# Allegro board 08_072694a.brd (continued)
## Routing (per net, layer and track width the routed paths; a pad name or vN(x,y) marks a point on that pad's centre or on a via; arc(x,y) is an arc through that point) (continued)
Net_82: length 0.9
  TOP w0.254: 125.22,56.64 v1(124.59,56.01)
PGOOD1: length 68
  TOP w0.254: R1.1 66.17,60.33 v1(66.68,59.82) U1.A8
  L5-INT3 w0.254: v1(66.68,59.82) 67.32,59.18 67.32,58.08 67.74,57.66 68.86,57.66 69.82,56.69 69.82,49.04 40.61,19.83 TP6.1
PGOOD2: length 37.2
  TOP w0.254: R16.1 37.46,60.33 v1(37.97,59.82) U2.A8
  L5-INT3 w0.254: TP21.1 33.56,61.21 34.96,59.82 v1(37.97,59.82)
PGOOD3: length 90.4
  TOP w0.254: R30.1 95.38,60.33 v1(95.88,59.82) U3.A8
  L4-INT2 w0.254: TP29.1 160.55,48.89 124.21,48.89 120.61,52.49 120.61,55.69 117.12,59.18 U3.A8 v1(95.88,59.82)
PGOOD4: length 54.4
  TOP w0.254: R44.1 124.08,60.33 v1(124.59,59.82) U4.A8
  L4-INT2 w0.254: v1(124.59,59.82) 125.2,59.21 163.35,59.21 TP37.1
RUN: length 163.6
  TOP w0.254: U1.B8 v1(67.94,59.82)
  L4-INT2 w0.254: v1(34.67,63.64) 22.31,63.64 2.11,43.44 2.11,33.07 TP5.1 2.42,27.44 2.42,22.71 P1.2
  L5-INT3 w0.254: v1(34.67,63.64) 34.67,63.18 37.39,60.46 67.19,60.46 67.84,59.82 v1(67.94,59.82) 68.53,59.23 86.08,59.23 87.98,57.34 91.35,57.34 v1(91.82,57.81) 112.76,57.81 116.88,61.93 v1(120.52,61.93)
  BOTTOM w0.254: v1(91.82,57.81) 92.33,58.32 R32.2 ; v1(34.67,63.64) 34.67,61.84 R18.2 ; v1(120.52,61.93) 120.68,61.77 R46.2
SOFTSTART: length 104.2
  TOP w0.254: U1.A11 v1(66.68,63.63) 65.91,62.86 C6.2 ; C32.2 37.21,62.86 v1(37.97,63.63) U2.A11 ; U4.A11 v1(124.59,63.63) 123.82,62.86 C78.2 ; U3.A11 v1(95.88,63.63) 95.12,62.86 C55.2
  L4-INT2 w0.254: v1(37.97,63.63) 38.63,62.97 56.04,62.97 56.55,62.46 56.99,62.46 57.5,62.97 62.03,62.97 62.38,62.61 65.66,62.61 v1(66.68,63.63) U1.A11 95.25,62.99 v1(95.88,63.63) 96.55,62.97 118.87,62.97 119.36,63.46 119.86,63.46 120.35,62.97 123.93,62.97 v1(124.59,63.63)
SYNC1: length 68.6
  TOP w0.254: U1.B6 v1(67.94,56.01) ; R58.2 v1(64.9,56.26)
  L3-INT1 w0.254: v1(64.9,56.26) 65.24,56.6 67.35,56.6 v1(67.94,56.01)
  L5-INT3 w0.254: v1(64.9,56.26) 64.21,55.58 64.21,50.75 24.46,11 TP8.1
UNNAMED_1_ADLTM4712_I1_COMPB: length 4.3
  TOP w0.254: U1.B11 v1(67.94,63.63)
  BOTTOM w0.203: R10.1 66,64.26 66.04,64.26
  BOTTOM w0.254: v1(67.94,63.63) 67.31,64.26 66.04,64.26
UNNAMED_1_ADLTM4712_I1_EXTVCC: length 10.6
  TOP w0.254: U1.B4 v1(67.94,53.47)
  BOTTOM w0.254: 67.27,55.08 67.31,55.04 67.31,54.1 v1(67.94,53.47) ; 67.27,55.08 C95.2 ; 67.27,55.08 66.97,55.38 66.19,55.38 65.91,55.66 63.85,55.66 63.17,56.34 R11.1
UNNAMED_1_ADLTM4712_I1_FREQ: length 3.6
  TOP w0.254: R3.2 64.35,58.55 v1(66.68,58.55) U1.A7
UNNAMED_1_ADLTM4712_I1_ISET: length 5.3
  TOP w0.254: U1.B5 v1(67.94,54.74) ; R6.2 v1(64.95,54.61)
  L3-INT1 w0.254: v1(67.94,54.74) 67.35,55.34 65.68,55.34 v1(64.95,54.61)
UNNAMED_1_ADLTM4712_I1_PHMODE: length 5.5
  TOP w0.254: U1.A9 v1(66.68,61.09)
  BOTTOM w0.254: v1(66.68,61.09) 66.04,60.45 66.04,58.71 R5.2 65.65,58.27 R4.1
UNNAMED_1_ADLTM4712_I1_SW1: length 3.6
  TOP w0.254: U1.K5 v1(79.38,54.74) U1.L5 v1(80.64,54.74)
  BOTTOM w0.254: U1.K5 v1(79.38,54.74)
UNNAMED_1_ADLTM4712_I1_SW2: length 3.6
  TOP w0.254: v1(80.64,59.82) U1.L8 v1(79.38,59.82) U1.K8
  BOTTOM w0.254: U1.K8 v1(79.38,59.82)
UNNAMED_1_ADLTM4712_I1_VOUT: length 130
  TOP w0.254: U1.H12 v1(76.84,64.9) ; U1.M12 v1(81.91,64.9) ; U1.K11 v1(79.38,63.63) ; U1.M11 v1(81.91,63.63) ; U1.L12 v1(80.64,64.9) ; U1.K12 v1(79.38,64.9) ; U1.L11 v1(80.64,63.63) ; U1.J12 v1(78.1,64.9) ; U1.J11 v1(78.1,63.63) ; U1.H11 v1(76.84,63.63)
  L3-INT1 w0.254: TP17.1 94.14,97.16 88.93,91.94 88.93,81.25 85.24,77.57 76.84,77.57 75.84,76.58 75.84,66.93 76.43,66.34 v2(77.44,66.34)
  L6-INT4 w0.254: 66.93,65.66 76.07,65.66 v1(76.84,64.9) ; 66.93,65.66 63.79,65.66 60.3,62.17 v1(60.3,57.55) ; 66.93,65.66 66.94,65.67 v1(66.94,68.72) 66.93,68.73 ; v2(79.5,76.33) 78.05,77.77 69.27,77.77 58.29,66.8 58.29,55.55 59.99,53.85 60.96,53.85 v1(61.34,54.23)
  BOTTOM w0.254: C14.2 v1(66.94,68.72) ; R11.2 v1(60.3,57.55) ; v1(61.34,54.23) 61.72,54.61 R13.1
  vias: v2(77.44,67.46) v2(78.49,75.44) v2(78.49,74.14) v2(78.46,73.02) v2(78.49,71.93) v2(78.49,69.54) v2(78.51,70.66) v2(78.51,68.45) v2(80.04,73.81) v2(80.9,76.33) v2(81.16,73.79) v2(82.17,73.79) v2(82.3,76.33) v2(83.82,76.33)
UNNAMED_1_CAP_I39_N1: length 1.7
  BOTTOM w0.254: R7.2 61.89,61.9 C11.1
UNNAMED_1_CN3P_I129_N3: length 4
  BOTTOM w0.254: R8.1 7.38,16.44 R9.2 5.07,18.08 P1.3
UNNAMED_1_CN3P_I130_N1: length 3
  BOTTOM w0.508: R2.2 8.01,43.05 P2.1
UNNAMED_2_ADLTM4712_I17_COMPA: length 23.4
  TOP w0.254: U2.B10 v1(39.24,62.36)
  L5-INT3 w0.254: v1(56.77,62.99) 39.88,62.99 v1(39.24,62.36)
  BOTTOM w0.254: v1(56.77,62.99) 57.57,63.79 R59.1 ; v1(39.24,62.36) 38.61,62.99 36.87,62.99 R23.2
UNNAMED_2_ADLTM4712_I17_COMPB: length 4.3
  TOP w0.254: U2.B11 v1(39.24,63.63)
  BOTTOM w0.254: v1(39.24,63.63) 38.61,64.26 37.3,64.26 R23.1
UNNAMED_2_ADLTM4712_I17_EXTVCC: length 10
  TOP w0.254: U2.B4 v1(39.24,53.47)
  BOTTOM w0.254: R24.1 34.46,56.35 35.26,55.55 36.88,55.55 37.09,55.35 38.37,55.35 38.57,55.15 ; C97.2 38.57,55.15 ; 38.57,55.15 38.62,55.09 38.62,54.09 v1(39.24,53.47)
UNNAMED_2_ADLTM4712_I17_FB: length 8
  TOP w0.254: U2.B9 v1(39.24,61.09)
  BOTTOM w0.254: v1(39.24,61.09) 39.88,61.72 39.88,66.33 R25.2 39.88,67.89 R26.2
UNNAMED_2_ADLTM4712_I17_FREQ: length 3.6
  TOP w0.254: R19.2 35.65,58.55 v1(37.97,58.55) U2.A7
UNNAMED_2_ADLTM4712_I17_ISET: length 5.3
  TOP w0.254: R22.2 v1(36.22,54.61) ; U2.B5 v1(39.24,54.74)
  L3-INT1 w0.254: v1(39.24,54.74) 38.62,55.36 36.97,55.36 v1(36.22,54.61)
UNNAMED_2_ADLTM4712_I17_PHMODE: length 5.5
  TOP w0.254: U2.A9 v1(37.97,61.09)
  BOTTOM w0.254: v1(37.97,61.09) 36.92,60.03 R21.2 36.95,58.27 R20.1
UNNAMED_2_ADLTM4712_I17_RUN: length 5.1
  TOP w0.254: U2.B8 v1(39.24,59.82)
  BOTTOM w0.254: v1(39.24,59.82) 38.6,60.46 38.6,61.53 38.42,61.71 R18.1
UNNAMED_2_ADLTM4712_I17_SW1: length 3.6
  TOP w0.254: U2.K5 v1(50.67,54.74) U2.L5 v1(51.94,54.74)
  BOTTOM w0.254: U2.K5 v1(50.67,54.74)
UNNAMED_2_ADLTM4712_I17_SW2: length 3.6
  TOP w0.254: v1(51.94,59.82) U2.L8 v1(50.67,59.82) U2.K8
  BOTTOM w0.254: U2.K8 v1(50.67,59.82)
UNNAMED_2_ADLTM4712_I17_SYNC: length 12.9
  TOP w0.254: U2.B6 v1(39.24,56.01) ; v1(36.22,56.16) 36.12,56.26 R17.1
  L3-INT1 w0.254: v1(36.22,56.16) 36.67,56.61 38.64,56.61 v1(39.24,56.01)
  L5-INT3 w0.254: v1(30.47,58.25) 32.56,56.16 v1(36.22,56.16)
  BOTTOM w0.254: C99.1 v1(30.47,58.25)
UNNAMED_2_ADLTM4712_I17_VOUT: length 76.6
  TOP w0.254: U2.H12 v1(48.13,64.9) ; U2.L12 v1(51.94,64.9) ; U2.K11 v1(50.67,63.63) ; U2.M12 v1(53.21,64.9) ; U2.M11 v1(53.21,63.63) ; U2.J11 v1(49.4,63.63) ; U2.L11 v1(51.94,63.63) ; U2.H11 v1(48.13,63.63) ; U2.K12 v1(50.67,64.9) ; U2.J12 v1(49.4,64.9)
  L6-INT4 w0.254: v1(32.61,54.18) 32.41,53.97 31.6,53.97 29.21,56.36 29.21,64.95 42.11,77.85 49.28,77.85 v2(50.8,76.33) ; v1(48.13,64.9) 47.5,65.53 33.78,65.53 31.28,63.03 v1(31.28,56.35)
  BOTTOM w0.254: R27.1 33.05,54.61 v1(32.61,54.18) ; R24.2 v1(31.28,56.35)
  vias: v2(48.9,67.34) v2(48.9,66.22) v2(49.78,75.44) v2(49.76,74.09) v2(49.74,72.97) v2(49.76,71.88) v2(49.78,70.61) v2(49.76,69.49) v2(49.78,68.4) v2(51.43,73.91) v2(52.2,76.33) v2(52.45,73.91) v2(53.39,73.89) v2(53.59,76.33) v2(55.12,76.33)
UNNAMED_3_ADLTM4712_I10_COMPA: length 11.4
  TOP w0.254: U3.B10 v1(97.16,62.36)
  BOTTOM w0.254: R60.1 87.87,64.59 93.18,64.59 R37.2 94.78,62.99 96.52,62.99 v1(97.16,62.36)
UNNAMED_3_ADLTM4712_I10_COMPB: length 4.3
  TOP w0.254: U3.B11 v1(97.16,63.63)
  BOTTOM w0.254: v1(97.16,63.63) 96.52,64.26 95.21,64.26 R37.1
UNNAMED_3_ADLTM4712_I10_EXTVCC: length 9.3
  TOP w0.254: U3.B4 v1(97.16,53.47)
  BOTTOM w0.254: 96.54,55.12 96.54,54.08 v1(97.16,53.47) ; 96.54,55.12 96.54,56.97 C101.2 ; 96.54,55.12 96.26,55.4 93.8,55.4 93.3,55.9 R38.1
UNNAMED_3_ADLTM4712_I10_FB: length 8
  TOP w0.254: U3.B9 v1(97.16,61.09)
  BOTTOM w0.254: R40.2 R39.2 97.79,66.36 97.79,61.72 v1(97.16,61.09)
UNNAMED_3_ADLTM4712_I10_FREQ: length 3.6
  TOP w0.254: R33.2 93.56,58.55 v1(95.88,58.55) U3.A7
UNNAMED_3_ADLTM4712_I10_ISET: length 5.4
  TOP w0.254: R36.2 94.01,54.61 v1(94.26,54.86) ; U3.B5 v1(97.16,54.74)
  L3-INT1 w0.254: v1(97.16,54.74) 96.44,55.45 94.84,55.45 v1(94.26,54.86)
UNNAMED_3_ADLTM4712_I10_PHMODE: length 3.6
  TOP w0.254: U3.A9 v1(95.88,61.09)
  BOTTOM w0.254: R34.1 94.65,59.74 R35.2 95.78,61.19 v1(95.88,61.09)
UNNAMED_3_ADLTM4712_I10_RUN: length 4
  TOP w0.254: U3.B8 v1(97.16,59.82)
  BOTTOM w0.254: R32.1 95.44,59.11 96.44,59.11 v1(97.16,59.82)
UNNAMED_3_ADLTM4712_I10_SW1: length 3.6
  TOP w0.254: U3.K5 v1(108.59,54.74) U3.L5 v1(109.85,54.74)
  BOTTOM w0.254: U3.K5 v1(108.59,54.74)
UNNAMED_3_ADLTM4712_I10_SW2: length 3.6
  TOP w0.254: U3.K8 v1(108.59,59.82) U3.L8 v1(109.85,59.82)
  BOTTOM w0.254: U3.K8 v1(108.59,59.82)
UNNAMED_3_ADLTM4712_I10_SYNC: length 12.9
  TOP w0.254: v1(94.26,56.25) 94.23,56.25 94.22,56.26 R31.1 ; U3.B6 v1(97.16,56.01)
  L3-INT1 w0.254: v1(97.16,56.01) 96.62,56.54 94.54,56.54 v1(94.26,56.25)
  L6-INT4 w0.254: v1(88.65,55.37) 88.65,55.93 89.76,57.05 91.41,57.05 92.21,56.25 v1(94.26,56.25)
  BOTTOM w0.254: C102.1 v1(88.65,55.37)
UNNAMED_3_ADLTM4712_I10_VOUT: length 78
  TOP w0.254: U3.J12 v1(107.31,64.9) ; U3.M12 v1(111.12,64.9) ; U3.M11 v1(111.12,63.63) ; U3.H11 v1(106.04,63.63) ; U3.H12 v1(106.04,64.9) ; U3.K12 v1(108.59,64.9) ; U3.L11 v1(109.85,63.63) ; U3.L12 v1(109.85,64.9) ; U3.K11 v1(108.59,63.63) ; U3.J11 v1(107.31,63.63)
  L6-INT4 w0.254: v1(90.68,54.1) 90.5,53.92 88.09,53.92 87.07,54.94 87.07,65.99 98.98,77.9 107.01,77.9 v2(108.59,76.33) ; v1(89.9,58.02) 89.9,64.24 91.19,65.53 105.41,65.53 v1(106.04,64.9)
  BOTTOM w0.254: v1(90.68,54.1) 91.19,54.61 R41.1 ; 91.61,56.31 R38.2 v1(89.9,58.02)
  vias: v2(106.73,67.44) v2(106.73,66.32) v2(107.7,75.44) v2(107.77,74.12) v2(107.75,73) v2(107.77,71.91) v2(107.8,70.64) v2(107.77,69.52) v2(107.8,68.43) v2(109.07,73.79) v2(109.98,76.33) v2(110.19,73.76) v2(111.28,73.79) v2(111.51,76.33) v2(113.03,76.33)
UNNAMED_4_ADLTM4712_I11_COMPA: length 10.9
  TOP w0.254: U4.B10 v1(125.86,62.36)
  BOTTOM w0.254: R61.1 116.88,64.74 120.24,64.74 121.58,63.41 R51.2 123.48,62.99 125.22,62.99 v1(125.86,62.36)
UNNAMED_4_ADLTM4712_I11_COMPB: length 4.3
  TOP w0.254: U4.B11 v1(125.86,63.63)
  BOTTOM w0.254: R51.1 123.91,64.26 125.22,64.26 v1(125.86,63.63)
UNNAMED_4_ADLTM4712_I11_EXTVCC: length 9.1
  TOP w0.254: U4.B4 v1(125.86,53.47)
  BOTTOM w0.254: R52.1 121.9,56.03 122.57,55.37 124.87,55.37 125.2,55.05 ; C104.2 125.2,57.01 125.2,55.05 ; v1(125.86,53.47) 125.2,54.13 125.2,55.05
UNNAMED_4_ADLTM4712_I11_FB: length 8
  TOP w0.254: U4.B9 v1(125.86,61.09)
  BOTTOM w0.254: v1(125.86,61.09) 126.49,61.72 R53.2 126.49,67.89 R54.2
UNNAMED_4_ADLTM4712_I11_FREQ: length 3.6
  TOP w0.254: U4.A7 v1(124.59,58.55) 122.26,58.55 R47.2
UNNAMED_4_ADLTM4712_I11_ISET: length 5.3
  TOP w0.254: R50.2 v1(122.83,54.61) ; U4.B5 v1(125.86,54.74)
  L3-INT1 w0.254: v1(122.83,54.61) 123.6,55.37 125.22,55.37 v1(125.86,54.74)
UNNAMED_4_ADLTM4712_I11_PHMODE: length 4.4
  TOP w0.254: U4.A9 v1(124.59,61.09)
  BOTTOM w0.254: v1(124.59,61.09) 123.47,59.97 R48.1 R49.2
UNNAMED_4_ADLTM4712_I11_RUN: length 4.9
  TOP w0.254: U4.B8 v1(125.86,59.82)
  BOTTOM w0.254: R46.1 124.89,61.77 125.22,61.44 125.22,60.45 v1(125.86,59.82)
UNNAMED_4_ADLTM4712_I11_SW1: length 3.6
  TOP w0.254: v1(138.56,54.74) U4.L5 v1(137.29,54.74) U4.K5
  BOTTOM w0.254: U4.K5 v1(137.29,54.74)
UNNAMED_4_ADLTM4712_I11_SW2: length 3.6
  TOP w0.254: U4.K8 v1(137.29,59.82) U4.L8 v1(138.56,59.82)
  BOTTOM w0.254: U4.K8 v1(137.29,59.82)
UNNAMED_4_ADLTM4712_I11_SYNC: length 12.6
  TOP w0.254: U4.B6 v1(125.86,56.01) ; R45.1 v1(122.91,56.26)
  L3-INT1 w0.254: v1(125.86,56.01) 125.17,56.69 123.34,56.69 v1(122.91,56.26)
  L5-INT3 w0.254: v1(122.91,56.26) 121.36,54.71 118.69,54.71 v1(117.81,55.6)
  BOTTOM w0.254: v1(117.81,55.6) 118.06,55.85 C105.1
UNNAMED_4_ADLTM4712_I11_VOUT: length 77.4
  TOP w0.254: U4.K12 v1(137.29,64.9) ; U4.M12 v1(139.83,64.9) ; U4.H12 v1(134.75,64.9) ; U4.J11 v1(136.02,63.63) ; U4.K11 v1(137.29,63.63) ; U4.H11 v1(134.75,63.63) ; U4.M11 v1(139.83,63.63) ; U4.L11 v1(138.56,63.63) ; U4.L12 v1(138.56,64.9) ; U4.J12 v1(136.02,64.9)
  L6-INT4 w0.254: v1(119.25,54.1) 119.08,53.92 117.92,53.92 116.2,55.64 116.2,66.93 127.13,77.85 135.76,77.85 v2(137.29,76.33) ; v1(120,57.7) 119.21,57.7 118.49,58.42 118.49,63.88 120.04,65.43 134.21,65.43 v1(134.75,64.9)
  BOTTOM w0.254: v1(119.25,54.1) 119.76,54.61 R55.1 ; R52.2 v1(120,57.7)
  vias: v2(135.46,67.44) v2(135.46,66.32) v2(136.27,75.44) v2(136.25,74.12) v2(136.22,73) v2(136.25,71.91) v2(136.27,70.64) v2(136.25,69.52) v2(136.27,68.43) v2(137.79,73.91) v2(138.81,76.33) v2(138.94,73.91) v2(140.08,73.91) v2(140.34,76.33) v2(141.86,76.33)
VOUT: length 176.5
  L6-INT4 w0.254: v2(108.59,79.76) 107.19,78.36 98.79,78.36 86.61,66.18 86.61,54.75 87.9,53.47 90.42,53.47 v1(90.68,53.21) ; v1(119.25,53.21) 119,53.47 117.73,53.47 115.75,55.45 115.75,67.12 126.94,78.31 135.84,78.31 v2(137.29,79.76) ; v1(32.61,53.31) 32.44,53.49 31.39,53.49 28.73,56.16 28.73,65.11 41.92,78.31 49.35,78.31 v2(50.8,79.76) ; v2(79.5,79.76) 77.98,78.23 69.08,78.23 57.84,66.99 57.84,55.32 59.82,53.34 61.09,53.34 v1(61.34,53.09)
  BOTTOM w0.254: R29.1 33.1,52.83 v1(32.61,53.31) ; v1(61.34,53.09) 61.6,52.83 R15.1 ; R57.1 119.63,52.83 v1(119.25,53.21) ; v1(90.68,53.21) 91.06,52.83 R43.1
  vias: v2(48.49,84.05) v2(48.51,80.77) v2(49.91,83.82) v2(49.91,80.9) v2(50.19,82.38) v2(50.67,89.66) v2(50.67,88.39) v2(50.67,87.12) v2(52.2,79.76) v2(53.59,79.76) v2(54.41,82.39) v2(54.48,81.03) v2(54.61,83.82) v2(54.74,89.66) v2(54.74,88.39) v2(54.74,87.12) v2(55.12,79.76) v2(56.01,80.77) v2(56.11,84.02) v2(60.2,89.79) v2(60.2,88.52) v2(60.2,87.25) v2(64.26,89.79) v2(64.26,88.52) v2(64.26,87.25) v2(68.96,89.79) v2(68.96,88.52) v2(68.96,87.25) v2(73.03,89.79) v2(73.03,88.52) v2(73.03,87.25) v2(77.17,84.04) v2(77.17,80.74) v2(78.61,89.66) v2(78.61,88.39) v2(78.61,87.12) v2(78.61,83.82) v2(78.61,81.03) v2(78.87,82.37) v2(80.9,79.76) v2(82.3,79.76) v2(82.68,89.66) v2(82.68,88.39) v2(82.68,87.12) v2(83.14,82.39) v2(83.31,81.03) v2(83.44,83.82) v2(83.82,79.76) v2(84.84,84.02) v2(84.84,80.65) v2(89.6,100.18) v2(89.6,98.02) v2(89.6,95.86) v2(90.49,99.04) v2(90.49,96.88) v2(91.82,89.92) v2(91.82,88.65) v2(91.82,87.38) v2(92.01,104.56) v2(92.01,101.51) v2(93.47,104.52) v2(93.47,101.47) v2(93.75,103.03) v2(98.55,89.92) v2(98.55,88.65) v2(98.55,87.38) v2(101.85,105.03) v2(101.85,103.76) v2(101.85,102.49) v2(101.85,101.22) v2(102.62,89.92) v2(102.62,88.65) v2(102.62,87.38) v2(106.38,84.05) v2(106.37,80.75) v2(107.44,89.66) v2(107.44,88.39) v2(107.44,87.12) v2(107.82,80.9) v2(107.95,83.82) v2(108.07,82.38) v2(108.31,96.11) v2(108.31,94.44) v2(109.58,96.11) v2(109.58,94.44) v2(109.98,79.76) v2(110.85,96.11) v2(110.85,94.44) v2(111.51,89.66) v2(111.51,88.39) v2(111.51,87.12) v2(111.51,79.76) v2(112.35,82.41) v2(112.52,83.82) v2(112.52,80.9) v2(113.03,79.76) v2(114.05,84.05) v2(114.04,80.75) v2(116.71,89.92) v2(116.71,88.65) v2(116.71,87.38) v2(117.09,105.16) v2(117.09,103.89) v2(117.09,102.62) v2(117.09,101.35) v2(120.78,89.92) v2(120.78,88.65) v2(120.78,87.38) v2(127.51,89.92) v2(127.51,88.65) v2(127.51,87.38) v2(131.57,89.92) v2(131.57,88.65) v2(131.57,87.38) v2(135.1,80.72) v2(135.1,84.02) v2(136.4,89.66) v2(136.4,88.39) v2(136.4,87.12) v2(136.53,83.82) v2(136.53,80.9) v2(136.8,82.36) v2(137.79,81.58) v2(138.81,79.76) v2(140,81.58) v2(140.34,79.76) v2(140.46,89.66) v2(140.46,88.39) v2(140.46,87.12) v2(141,82.39) v2(141.22,83.82) v2(141.22,80.9) v2(141.86,79.76) v2(142.7,80.72) v2(142.7,84.02)

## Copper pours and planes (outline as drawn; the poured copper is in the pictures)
GND_POWER on TOP: 1.27,1.27 1.27,113.03 88.32,113.03 88.54,112.8 88.54,113.03 144.86,113.03 144.86,112.73 145.16,113.03 176.53,113.03 176.53,1.27 121.26,1.27 120.93,1.6 120.93,1.27 89.94,1.27 89.94,1.75 89.46,1.27
GND_POWER on BOTTOM: 1.27,1.27 1.27,113.03 88.32,113.03 88.54,112.8 88.54,113.03 144.86,113.03 144.86,112.73 145.16,113.03 176.53,113.03 176.53,1.27 121.26,1.27 120.93,1.6 120.93,1.27 89.94,1.27 89.94,1.75 89.46,1.27 ; 11 cut-outs
GND_POWER on L2-GND, L4-INT2, L5-INT3, L6-INT4, L7-GND: 1.27,1.27 1.27,113.03 176.53,113.03 176.53,1.27
GND_POWER on L3-INT1: 1.27,1.27 1.27,113.03 176.53,113.03 176.53,1.27 ; 2 cut-outs
GND_SIGNAL on L3-INT1: outline of 149 points within 32,48.71 129.06,68.51
VIN on TOP: 134.47,51.74 141.93,51.74 142.31,51.36 142.31,19.61 141.88,19.18 120.85,19.18 120.55,18.87 120.55,1.6 120.22,1.27 90.8,1.27 90.32,1.75 90.32,26.78 89.98,27.12 47.76,27.12 47.5,27.38 47.5,51.44 47.8,51.74 53.92,51.74 53.92,51.74 55.14,51.74 55.7,51.18 55.7,40.06 56.17,39.59 75.77,39.59 76.28,40.11 76.27,51.18 76.27,51.59 76.42,51.74 76.84,51.74 76.84,51.74 84.11,51.74 84.39,51.45 84.39,40.02 84.89,39.52 105.1,39.52 105.58,39.99 105.58,51.2 105.58,51.59 105.72,51.74 106.12,51.74 106.12,51.74 113.41,51.74 113.66,51.49 113.66,39.84 114.02,39.47 133.65,39.47 134.24,40.06 134.24,51.5
VIN on BOTTOM: 134.47,51.74 141.93,51.74 142.31,51.36 142.31,19.61 141.88,19.18 120.85,19.18 120.55,18.87 120.55,1.61 120.21,1.27 90.8,1.27 90.32,1.75 90.32,26.78 89.98,27.12 47.76,27.12 47.5,27.38 47.5,51.64 47.6,51.74 55.14,51.74 55.7,51.18 55.7,40.07 56.17,39.59 75.77,39.59 76.28,40.11 76.27,51.18 76.84,51.74 84.06,51.74 84.39,51.41 84.39,40.03 84.89,39.52 105.1,39.52 105.58,39.99 105.58,51.2 106.12,51.74 113.29,51.74 113.67,51.36 113.67,39.83 114.02,39.47 133.65,39.47 134.24,40.06 134.24,51.5
UNNAMED_1_ADLTM4712_I1_VOUT on TOP: 76.19,62.79 76.07,62.9 76.07,78.02 76.27,78.23 84.18,78.23 84.4,78 84.4,62.97 84.23,62.79
UNNAMED_1_ADLTM4712_I1_VOUT on BOTTOM: 76.19,62.79 76.07,62.9 76.07,78.02 76.27,78.23 84.13,78.23 84.18,78.23 84.4,78.01 84.4,62.97 84.23,62.79
UNNAMED_2_ADLTM4712_I17_VOUT on TOP: 47.46,62.79 47.37,62.88 47.37,77.72 47.7,78.06 55.5,78.06 55.7,77.85 55.7,63.04 55.45,62.79
UNNAMED_2_ADLTM4712_I17_VOUT on BOTTOM: 47.46,62.79 47.37,62.88 47.37,77.72 47.7,78.06 55.5,78.06 55.7,77.85 55.7,63.04 55.45,62.79
UNNAMED_3_ADLTM4712_I10_VOUT on TOP: 105.42,62.79 105.28,62.93 105.28,78.13 105.39,78.24 113.43,78.24 113.64,78.03 113.64,63.37 113.06,62.79
UNNAMED_3_ADLTM4712_I10_VOUT on BOTTOM: 105.42,62.79 105.28,62.93 105.28,78.13 105.39,78.23 113.43,78.23 113.64,78.03 113.64,63.37 113.06,62.79
UNNAMED_4_ADLTM4712_I11_VOUT on TOP: 141.96,78 142.32,77.65 142.32,63.2 141.91,62.79 134.12,62.79 133.98,62.92 133.98,77.75 134.24,78
UNNAMED_4_ADLTM4712_I11_VOUT on BOTTOM: 141.96,78 142.32,77.65 142.32,63.2 141.91,62.79 134.12,62.79 133.98,62.92 133.98,77.75 134.24,78
VOUT on TOP: 144.48,79.2 143.94,78.66 134.49,78.66 133.73,79.43 133.73,84.89 133.3,85.32 115.87,85.32 115.37,84.81 115.37,79.22 114.81,78.66 105.33,78.66 105,78.99 105,85.06 104.72,85.34 86.44,85.34 86.11,85.01 86.11,79.4 85.37,78.66 76.23,78.66 75.9,78.99 75.9,84.96 75.51,85.34 57.99,85.34 57.68,85.04 57.68,78.99 57.33,78.64 47.63,78.64 47.19,79.08 47.19,94.89 47.43,95.14 88.52,95.14 88.93,95.54 88.93,112.79 89.17,113.03 144.24,113.03 144.48,112.79
VOUT on BOTTOM: 144.48,79.2 143.94,78.66 134.52,78.66 133.73,79.45 133.73,84.89 133.3,85.32 115.87,85.32 115.37,84.81 115.37,79.22 114.81,78.66 105.33,78.66 105,78.99 105,85.34 86.44,85.34 86.11,85.01 86.11,79.4 85.37,78.66 76.23,78.66 75.9,78.99 75.9,84.96 75.51,85.34 57.99,85.34 57.68,85.04 57.68,78.99 57.33,78.64 47.63,78.64 47.19,79.08 47.19,94.9 47.42,95.13 88.53,95.13 88.93,95.53 88.93,112.79 89.17,113.03 144.24,113.03 144.48,112.79

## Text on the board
Ref Des/Silkscreen Top: ON | RUN | OFF | PS | MODE | FCM | SGND | GND | IMON2 | PGOOD2 | SYNC1 | IMON1 | PGOOD1 | VOUT | VIN | 12V / 48A | 5V - 36V | PGOOD4 | PGOOD3 | IMON3 | IMON4 | BUCK-BOOT POWER uMODULE REGULATOR | HIGH DENSITY POLYPHASE | EVAL-LTM4712-A   Z | LTM4712
PAGE_OUTLINE: 1 | POWER uMODULE REGULATOR | HIGH DENSITY POLYPHASE BUCK-BOOT
User.15: .0028" | .0059" | .0035" | GROUND / INTERNAL3  (LAYER 5) | GROUND / INTERNAL4  (LAYER 6) | GROUND              (LAYER 7) | SECONDARY SIDE      (LAYER 8) | SECONDARY SOLDER MASK | SECONDARY SILKSCREEN | SOLDERMASK DEFINE;     DESIGN HAS SOLDER MASK DEFINED PADS ON U1-U4 | DO NOT CHANGE ANY SIZE ON THIS COMPONENT. | WITH 0.0287"PAD,0.0248" SOLDER MASK, AND 0.0236" SOLDER PASTE. | PER IPC-4552 LATEST REVISION | ENIG (Electroless Nickel/Immersion Gold)
User.18: L2-GND | 08-      -08
User.19: L3-INT1 | 08-      -09
User.20: L4-INT2 | 08-      -10
User.23: L5-INT3 | 08-      -11
User.24: L6-INT4 | 08-      -12
User.25: L7-GND | 08-      -13
User.28: V | LOAD | IN | A | 5V-36V
User.33: A
User.45: FIGURE | SIZE | 10.0 | 12.0 | 40.0 | 100.0 | 213.0 | 187.0 | PLATED | NON-PLATED | FINISHED HOLES IN MILS | ALL UNITS ARE IN MILS | QTY | 617 | 673 | 6 | 17 | 4 | TOLERANCE/NOTES
